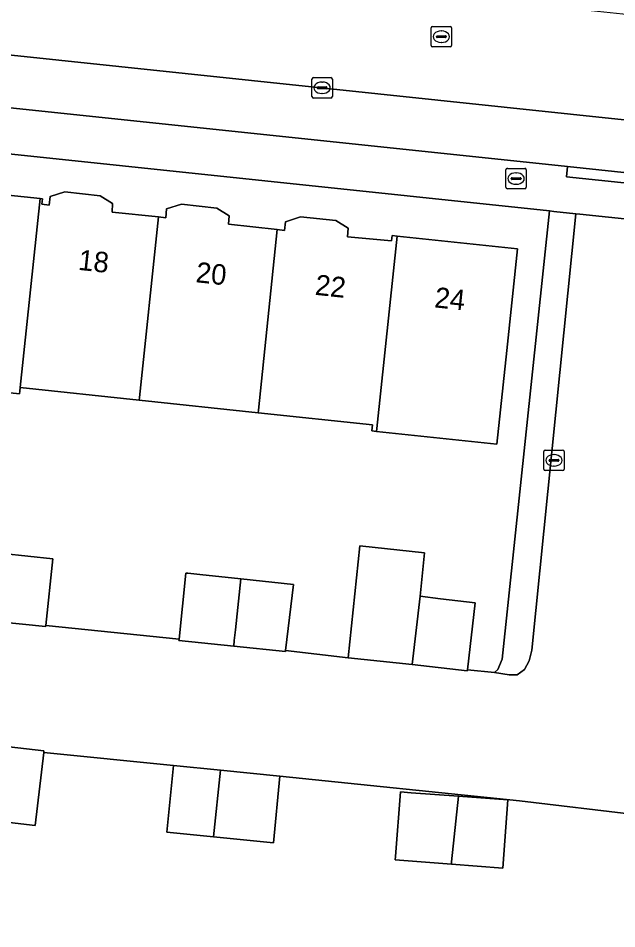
# Model space of a CAD drawing. Extents: x 163008 to 163854, y 382777 to 383982.
# Drawn here: x 163302.95 to 163332.24, y 383285.09 to 383329.64 of the extents above; entities that cross this region are included whole.
import ezdxf

# ---------------------------------------------------------------- set-up
doc = ezdxf.new("R2010")
doc.units = 0
for name, color, linetype in [('IMGEO_Brandkraan', 7, 'Continuous'), ('IMGEO_Erf', 7, 'Continuous'), ('IMGEO_Kolk', 7, 'Continuous'), ('IMGEO_Pand', 7, 'Continuous'), ('IMGEO_Pand_nummerreeks', 7, 'Continuous'), ('IMGEO_Parkeervlak_open', 7, 'Continuous'), ('IMGEO_Rijbaan_lokaal_open', 7, 'Continuous'), ('IMGEO_Rioolput', 7, 'Continuous'), ('IMGEO_Voetpad_open', 7, 'Continuous')]:
    doc.layers.add(name, color=color, linetype=linetype)

msp = doc.modelspace()

# ---------------------------------------------------------------- linework, layer by layer
at = {"layer": 'IMGEO_Brandkraan'}
for p, q in [((163326.815, 383321.366), (163326.815, 383322.218)), ((163326.89, 383322.292), (163327.742, 383322.292)), ((163327.816, 383322.218), (163327.816, 383321.366)), ((163327.074, 383321.786), (163327.074, 383321.798)), ((163327.512, 383321.749), (163327.114, 383321.749)), ((163327.117, 383321.835), (163327.515, 383321.835)), ((163327.303, 383322.072), (163327.328, 383322.072)), ((163327.558, 383321.798), (163327.558, 383321.786)), ((163327.742, 383321.292), (163326.89, 383321.292)), ((163327.326, 383321.512), (163327.301, 383321.512))]:
    msp.add_line(p, q, dxfattribs=at)
for points in [[(163326.815, 383321.366), (163326.815, 383322.218)], [(163326.89, 383322.292), (163327.742, 383322.292)], [(163327.816, 383322.218), (163327.816, 383321.366)], [(163327.742, 383321.292), (163326.89, 383321.292)]]:
    msp.add_lwpolyline(points, dxfattribs=at)
for centre, radius, start, end in [((163326.892, 383322.216), 0.0765, 91.552, 178.448), ((163326.892, 383322.216), 0.0765, 91.552, 178.448), ((163327.74, 383322.216), 0.0765, 1.552, 88.448), ((163327.74, 383322.216), 0.0765, 1.552, 88.448), ((163327.114, 383321.795), 0.0403, 85.8775, 175.7526), ((163327.111, 383321.785), 0.0366, 178.938, 274.7102), ((163327.515, 383321.792), 0.043, 264.8664, 352.4533), ((163327.519, 383321.797), 0.0386, 1.7309, 96.639), ((163326.892, 383321.368), 0.0765, 181.552, 268.448), ((163326.892, 383321.368), 0.0765, 181.552, 268.448), ((163327.74, 383321.368), 0.0765, 271.552, 358.448), ((163327.74, 383321.368), 0.0765, 271.552, 358.448)]:
    msp.add_arc(centre, radius, start, end, dxfattribs=at)
for centre, major_axis, ratio, start_param, end_param in [((163327.302, 383321.792), (-0.387, 0.002), 0.722429, 4.712389, 7.853982), ((163327.327, 383321.792), (-0.39, 0.002), 0.717154, 1.570796, 4.712389)]:
    msp.add_ellipse(centre, major_axis=major_axis, ratio=ratio, start_param=start_param, end_param=end_param, dxfattribs=at)
at = {"layer": 'IMGEO_Erf'}
for points in [[(163328.943, 383320.208), (163258.982, 383327.582)], [(163298.219, 383321.425), (163304.03, 383320.81), (163304.137, 383320.799), (163304.11, 383320.545), (163304.47, 383320.483), (163304.515, 383320.918), (163305.228, 383321.14), (163306.962, 383320.952), (163307.575, 383320.578), (163307.545, 383320.153), (163309.811, 383319.914), (163310.18, 383319.875), (163310.215, 383320.318), (163310.942, 383320.544), (163312.671, 383320.347), (163313.276, 383319.975), (163313.239, 383319.555), (163315.632, 383319.295), (163315.992, 383319.256), (163316.036, 383319.673), (163316.77, 383319.913), (163318.493, 383319.738), (163319.107, 383319.37), (163319.067, 383318.933), (163321.225, 383318.738), (163321.257, 383318.999), (163321.493, 383318.974), (163327.379, 383318.36), (163326.856, 383313.388), (163326.373, 383308.803), (163320.492, 383309.423), (163320.257, 383309.448), (163320.289, 383309.747), (163314.701, 383310.336), (163308.869, 383310.95), (163303.047, 383311.563), (163303.029, 383311.394), (163303.016, 383311.264), (163297.203, 383311.876)], [(163302.206, 383303.442), (163304.643, 383303.183), (163304.301, 383299.935), (163310.824, 383299.254), (163311.164, 383302.49), (163311.255, 383302.48), (163311.838, 383302.418), (163313.843, 383302.206), (163316.417, 383301.932), (163316.04, 383298.71), (163319.093, 383298.348), (163319.663, 383303.818), (163322.833, 383303.487), (163322.623, 383301.354), (163323.624, 383301.237), (163325.315, 383301.04), (163324.931, 383297.758), (163326.256, 383297.63), (163326.43, 383297.772), (163326.632, 383298.284), (163328.943, 383320.208)], [(163253.685, 383276.401), (163334.658, 383264.168), (163337.516, 383290.164), (163336.092, 383290.332), (163336.046, 383289.91), (163335.73, 383287.002), (163332.932, 383287.306), (163333.066, 383288.538), (163333.297, 383290.663), (163333.239, 383290.669), (163327.49, 383291.348), (163315.763, 383292.563), (163315.439, 383289.298), (163312.515, 383289.589), (163310.225, 383289.816), (163310.549, 383293.081), (163304.2, 383293.711), (163303.785, 383290.139), (163300.841, 383290.481), (163298.433, 383290.761), (163298.858, 383294.419)]]:
    msp.add_lwpolyline(points, dxfattribs=at)
msp.add_lwpolyline([(163321.657, 383291.785), (163322.19, 383291.745), (163324.499, 383291.572), (163326.915, 383291.391), (163326.666, 383288.061), (163324.15, 383288.25), (163321.407, 383288.456), (163321.42, 383288.622)], close=True, dxfattribs=at)
at = {"layer": 'IMGEO_Kolk'}
for p, q in [((163317.324, 383325.806), (163317.324, 383326.658)), ((163317.399, 383326.732), (163318.251, 383326.732)), ((163318.325, 383326.658), (163318.325, 383325.806)), ((163317.583, 383326.226), (163317.583, 383326.238)), ((163318.021, 383326.189), (163317.623, 383326.189)), ((163317.626, 383326.275), (163318.024, 383326.275)), ((163317.812, 383326.512), (163317.837, 383326.512)), ((163318.067, 383326.238), (163318.067, 383326.226)), ((163318.251, 383325.732), (163317.399, 383325.732)), ((163317.835, 383325.952), (163317.81, 383325.952)), ((163328.668, 383307.58), (163328.668, 383308.432)), ((163328.743, 383308.506), (163329.595, 383308.506)), ((163329.669, 383308.432), (163329.669, 383307.58)), ((163328.927, 383308), (163328.927, 383308.012)), ((163329.365, 383307.963), (163328.967, 383307.963)), ((163328.97, 383308.049), (163329.368, 383308.049)), ((163329.156, 383308.286), (163329.181, 383308.286)), ((163329.411, 383308.012), (163329.411, 383308)), ((163329.595, 383307.506), (163328.743, 383307.506)), ((163329.179, 383307.726), (163329.154, 383307.726))]:
    msp.add_line(p, q, dxfattribs=at)
for points in [[(163317.324, 383325.806), (163317.324, 383326.658)], [(163317.399, 383326.732), (163318.251, 383326.732)], [(163318.325, 383326.658), (163318.325, 383325.806)], [(163318.251, 383325.732), (163317.399, 383325.732)], [(163328.668, 383307.58), (163328.668, 383308.432)], [(163328.743, 383308.506), (163329.595, 383308.506)], [(163329.669, 383308.432), (163329.669, 383307.58)], [(163329.595, 383307.506), (163328.743, 383307.506)]]:
    msp.add_lwpolyline(points, dxfattribs=at)
for centre, radius, start, end in [((163317.401, 383326.656), 0.0765, 91.552, 178.448), ((163317.401, 383326.656), 0.0765, 91.552, 178.448), ((163318.249, 383326.656), 0.0765, 1.552, 88.448), ((163318.249, 383326.656), 0.0765, 1.552, 88.448), ((163317.623, 383326.235), 0.0403, 85.8775, 175.7526), ((163317.62, 383326.225), 0.0366, 178.938, 274.7102), ((163318.024, 383326.232), 0.043, 264.8664, 352.4533), ((163318.028, 383326.237), 0.0386, 1.7309, 96.639), ((163317.401, 383325.808), 0.0765, 181.552, 268.448), ((163317.401, 383325.808), 0.0765, 181.552, 268.448), ((163318.249, 383325.808), 0.0765, 271.552, 358.448), ((163318.249, 383325.808), 0.0765, 271.552, 358.448), ((163328.745, 383308.43), 0.0765, 91.552, 178.448), ((163328.745, 383308.43), 0.0765, 91.552, 178.448), ((163329.593, 383308.43), 0.0765, 1.552, 88.448), ((163329.593, 383308.43), 0.0765, 1.552, 88.448), ((163328.967, 383308.009), 0.0403, 85.8775, 175.7526), ((163328.964, 383307.999), 0.0366, 178.938, 274.7102), ((163329.368, 383308.006), 0.043, 264.8664, 352.4533), ((163329.372, 383308.011), 0.0386, 1.7309, 96.639), ((163328.745, 383307.582), 0.0765, 181.552, 268.448), ((163328.745, 383307.582), 0.0765, 181.552, 268.448), ((163329.593, 383307.582), 0.0765, 271.552, 358.448), ((163329.593, 383307.582), 0.0765, 271.552, 358.448)]:
    msp.add_arc(centre, radius, start, end, dxfattribs=at)
for centre, major_axis, ratio, start_param, end_param in [((163317.811, 383326.232), (-0.387, 0.002), 0.722429, 4.712389, 7.853982), ((163317.836, 383326.232), (-0.39, 0.002), 0.717154, 1.570796, 4.712389), ((163329.155, 383308.006), (-0.387, 0.002), 0.722429, 4.712389, 7.853982), ((163329.18, 383308.006), (-0.39, 0.002), 0.717154, 1.570796, 4.712389)]:
    msp.add_ellipse(centre, major_axis=major_axis, ratio=ratio, start_param=start_param, end_param=end_param, dxfattribs=at)
at = {"layer": 'IMGEO_Pand'}
for points in [[(163304.03, 383320.81), (163298.219, 383321.425), (163297.217, 383312.005), (163297.203, 383311.876), (163303.016, 383311.264), (163303.029, 383311.394), (163303.047, 383311.563)], [(163309.811, 383319.914), (163307.545, 383320.153), (163307.575, 383320.578), (163306.962, 383320.952), (163305.228, 383321.14), (163304.515, 383320.918), (163304.47, 383320.483), (163304.11, 383320.545), (163304.137, 383320.799), (163304.03, 383320.81), (163303.047, 383311.563), (163308.869, 383310.95), (163308.883, 383311.081)], [(163308.869, 383310.95), (163314.701, 383310.336), (163314.715, 383310.468), (163315.632, 383319.295), (163313.239, 383319.555), (163313.276, 383319.975), (163312.671, 383320.347), (163310.942, 383320.544), (163310.215, 383320.318), (163310.18, 383319.875), (163309.811, 383319.914), (163308.883, 383311.081)], [(163314.701, 383310.336), (163320.289, 383309.747), (163320.257, 383309.448), (163320.492, 383309.423), (163320.506, 383309.557), (163321.493, 383318.974), (163321.257, 383318.999), (163321.225, 383318.738), (163319.067, 383318.933), (163319.107, 383319.37), (163318.493, 383319.738), (163316.77, 383319.913), (163316.036, 383319.673), (163315.992, 383319.256), (163315.632, 383319.295), (163314.715, 383310.468)], [(163321.493, 383318.974), (163320.506, 383309.557), (163320.492, 383309.423), (163326.373, 383308.803), (163326.856, 383313.388), (163327.379, 383318.36)], [(163302.206, 383303.442), (163301.949, 383301.002), (163301.891, 383300.448), (163301.857, 383300.128), (163304.295, 383299.876), (163304.301, 383299.935), (163304.643, 383303.183)], [(163319.093, 383298.348), (163322.233, 383298.02), (163322.623, 383301.354), (163322.833, 383303.487), (163319.663, 383303.818)], [(163313.843, 383302.206), (163311.838, 383302.418), (163311.255, 383302.48), (163311.164, 383302.49), (163310.824, 383299.254), (163310.818, 383299.201), (163313.498, 383298.923), (163313.526, 383299.191), (163313.581, 383299.715)], [(163313.843, 383302.206), (163313.581, 383299.715), (163313.526, 383299.191), (163313.498, 383298.923), (163316.034, 383298.661), (163316.04, 383298.71), (163316.417, 383301.932)], [(163322.623, 383301.354), (163322.233, 383298.02), (163324.925, 383297.706), (163324.931, 383297.758), (163325.315, 383301.04), (163323.624, 383301.237)], [(163304.2, 383293.711), (163304.21, 383293.798), (163301.228, 383294.144), (163300.877, 383290.804), (163300.841, 383290.481), (163303.785, 383290.139)], [(163312.515, 383289.589), (163312.858, 383292.852), (163310.549, 383293.081), (163310.225, 383289.816)], [(163312.515, 383289.589), (163315.439, 383289.298), (163315.763, 383292.563), (163312.858, 383292.852)], [(163324.499, 383291.572), (163322.19, 383291.745), (163321.657, 383291.785), (163321.42, 383288.622), (163321.407, 383288.456), (163324.15, 383288.25), (163324.162, 383288.358)], [(163324.499, 383291.572), (163324.162, 383288.358), (163324.15, 383288.25), (163326.666, 383288.061), (163326.915, 383291.391)]]:
    msp.add_lwpolyline(points, close=True, dxfattribs=at)
at = {"layer": 'IMGEO_Parkeervlak_open'}
for points in [[(163357.869, 383321.869), (163357.191, 383321.885), (163345.01, 383323.363), (163342.345, 383323.645), (163264.288, 383331.894), (163261.682, 383332.169), (163260.519, 383332.292)], [(163264.588, 383329.254), (163329.829, 383322.377), (163337.498, 383321.569), (163353.697, 383319.861)]]:
    msp.add_lwpolyline(points, dxfattribs=at)
at = {"layer": 'IMGEO_Rijbaan_lokaal_open'}
msp.add_lwpolyline([(163308.306, 383332.445), (163294.491, 383333.86), (163294.277, 383333.901), (163264.838, 383337.06), (163264.288, 383331.894), (163342.345, 383323.645), (163342.881, 383328.717), (163338.995, 383329.144), (163338.661, 383329.18), (163334.627, 383329.617), (163334.51, 383329.629), (163332.849, 383329.802), (163325.729, 383330.567)], close=True, dxfattribs=at)
for points in [[(163336.363, 383319.426), (163330.432, 383320.051), (163330.245, 383320.071), (163328.091, 383298.714), (163327.956, 383298.193), (163327.734, 383297.779), (163327.37, 383297.508), (163326.976, 383297.508), (163326.256, 383297.63), (163324.931, 383297.758), (163324.925, 383297.706), (163322.233, 383298.02), (163319.093, 383298.348), (163316.04, 383298.71), (163316.034, 383298.661), (163313.498, 383298.923), (163310.818, 383299.201), (163310.824, 383299.254), (163304.301, 383299.935), (163304.295, 383299.876), (163301.857, 383300.128)], [(163301.228, 383294.144), (163304.21, 383293.798), (163304.2, 383293.711), (163310.549, 383293.081), (163312.858, 383292.852), (163315.763, 383292.563), (163327.49, 383291.348), (163333.239, 383290.669)]]:
    msp.add_lwpolyline(points, dxfattribs=at)
at = {"layer": 'IMGEO_Rioolput'}
for p, q in [((163323.159, 383328.306), (163323.159, 383329.158)), ((163323.234, 383329.232), (163324.086, 383329.232)), ((163323.647, 383329.012), (163323.672, 383329.012)), ((163324.16, 383329.158), (163324.16, 383328.306)), ((163323.418, 383328.726), (163323.418, 383328.738)), ((163323.856, 383328.689), (163323.458, 383328.689)), ((163323.461, 383328.775), (163323.859, 383328.775)), ((163323.67, 383328.452), (163323.645, 383328.452)), ((163323.902, 383328.738), (163323.902, 383328.726)), ((163324.086, 383328.232), (163323.234, 383328.232))]:
    msp.add_line(p, q, dxfattribs=at)
for points in [[(163323.159, 383328.306), (163323.159, 383329.158)], [(163323.234, 383329.232), (163324.086, 383329.232)], [(163324.16, 383329.158), (163324.16, 383328.306)], [(163324.086, 383328.232), (163323.234, 383328.232)]]:
    msp.add_lwpolyline(points, dxfattribs=at)
for centre, radius, start, end in [((163323.236, 383329.156), 0.0765, 91.552, 178.448), ((163323.236, 383329.156), 0.0765, 91.552, 178.448), ((163324.084, 383329.156), 0.0765, 1.552, 88.448), ((163324.084, 383329.156), 0.0765, 1.552, 88.448), ((163323.458, 383328.735), 0.0403, 85.8775, 175.7526), ((163323.455, 383328.725), 0.0366, 178.938, 274.7102), ((163323.859, 383328.732), 0.043, 264.8664, 352.4533), ((163323.863, 383328.737), 0.0386, 1.7309, 96.639), ((163323.236, 383328.308), 0.0765, 181.552, 268.448), ((163323.236, 383328.308), 0.0765, 181.552, 268.448), ((163324.084, 383328.308), 0.0765, 271.552, 358.448), ((163324.084, 383328.308), 0.0765, 271.552, 358.448)]:
    msp.add_arc(centre, radius, start, end, dxfattribs=at)
for centre, major_axis, ratio, start_param, end_param in [((163323.646, 383328.732), (-0.387, 0.002), 0.722429, 4.712389, 7.853982), ((163323.671, 383328.732), (-0.39, 0.002), 0.717154, 1.570796, 4.712389)]:
    msp.add_ellipse(centre, major_axis=major_axis, ratio=ratio, start_param=start_param, end_param=end_param, dxfattribs=at)
at = {"layer": 'IMGEO_Voetpad_open'}
for points in [[(163353.697, 383319.861), (163337.498, 383321.569), (163337.446, 383321.072), (163329.777, 383321.88), (163329.829, 383322.377), (163264.588, 383329.254)], [(163258.982, 383327.582), (163328.943, 383320.208), (163329.161, 383320.185), (163330.245, 383320.071), (163330.432, 383320.051), (163336.363, 383319.426), (163342.638, 383318.756), (163356.656, 383317.295), (163361.776, 383316.761)]]:
    msp.add_lwpolyline(points, dxfattribs=at)
for points in [[(163337.498, 383321.569), (163329.829, 383322.377), (163329.777, 383321.88), (163337.446, 383321.072)], [(163330.245, 383320.071), (163329.161, 383320.185), (163328.943, 383320.208), (163326.632, 383298.284), (163326.43, 383297.772), (163326.256, 383297.63), (163326.976, 383297.508), (163327.37, 383297.508), (163327.734, 383297.779), (163327.956, 383298.193), (163328.091, 383298.714)]]:
    msp.add_lwpolyline(points, close=True, dxfattribs=at)

# ---------------------------------------------------------------- texts
at = {"layer": 'IMGEO_Pand_nummerreeks'}
for s, rotation, p in [('18', 353.9897, (163305.86, 383317.329)), ('20', 353.9873, (163311.611, 383316.723)), ('22', 353.9873, (163317.447, 383316.108)), ('24', 353.9873, (163323.292, 383315.493))]:
    msp.add_text(s, height=1, rotation=rotation, dxfattribs=at).set_placement(p)

doc.saveas('drawing.dxf')
